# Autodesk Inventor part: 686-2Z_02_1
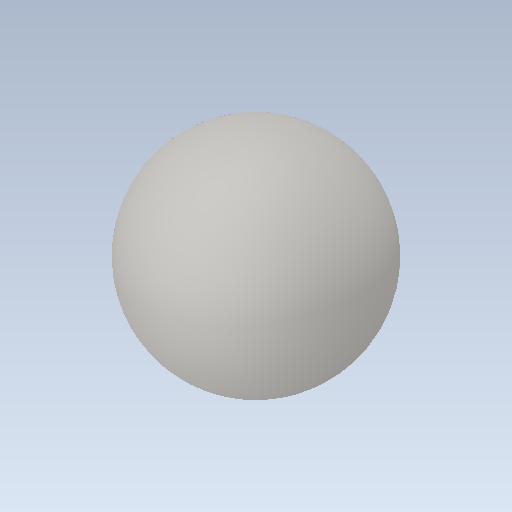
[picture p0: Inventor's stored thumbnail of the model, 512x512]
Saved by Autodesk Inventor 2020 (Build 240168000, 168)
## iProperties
Created: 2017-11
Part Number: 686-2Z_02_1
Material: Ogólny
Document SubType Name: Modeling
Designer: Tomasz
Density: 1 g/cm^3
Appearance: Domyślna
Sending System: SolidWorks 2017
Last Author: Tomasz
Last Saved: 2017-11-19
Source: 686-2Z_02_1
Author: Tomasz
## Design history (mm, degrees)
feature "Imported1"
node "Bryła1"
